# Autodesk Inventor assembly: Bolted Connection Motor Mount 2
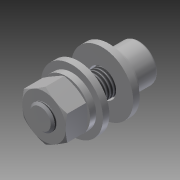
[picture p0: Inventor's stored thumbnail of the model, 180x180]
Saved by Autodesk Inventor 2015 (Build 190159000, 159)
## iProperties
Created: 2007-02
Part Number: Bolted Connection Motor Mount 2
Document SubType Name: Assembly
Designer: Autodesk, Inc.
Mass: 17.5979 g
Surface Area: 26.518 cm^2
Volume: 2.23891 cm^3
Density: 7.86 g/cm^3
ClientObjectVersion: 1
Author: Autodesk, Inc.
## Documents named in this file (5)
- C:\Users\Public\Documents\Autodesk\Inventor 2015\Samples\Models\Assemblies\Blower\Blower\Design Accelerator\Bolted Connection Motor Mount 11.iam
- C:\Users\Public\Documents\Autodesk\Inventor 2015\Samples\Standard Parts\en-US\ANSI B18.22.1\ANSI B18.22.1 - 1_4 - narrow - Type A.ipt
- C:\Users\Public\Documents\Autodesk\Inventor 2015\Samples\Standard Parts\en-US\ANSI B18.21.1\ANSI B18.21.1 - 0.25.ipt
- C:\Users\Public\Documents\Autodesk\Inventor 2015\Samples\Standard Parts\en-US\ANSI B18.3(13)\ANSI B18.3 - 1_4-28 UNF - 0.75(22).ipt
- C:\Users\Public\Documents\Autodesk\Inventor 2015\Samples\Standard Parts\en-US\ANSI B18.2.2(09)\ANSI B18.2.2 - 1_4 - 28(2).ipt
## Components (6 placed, 4 different names)
1. ANSI B18.22.1 - 1/4 - narrow - Type A:1
2. ANSI B18.21.1 - 0.25:2
3. ANSI B18.3 - 1/4-28 UNF - 0.75:3
4. ANSI B18.22.1 - 1/4 - narrow - Type A:4
5. ANSI B18.21.1 - 0.25:5
6. ANSI B18.2.2 - 1/4 - 28:6
